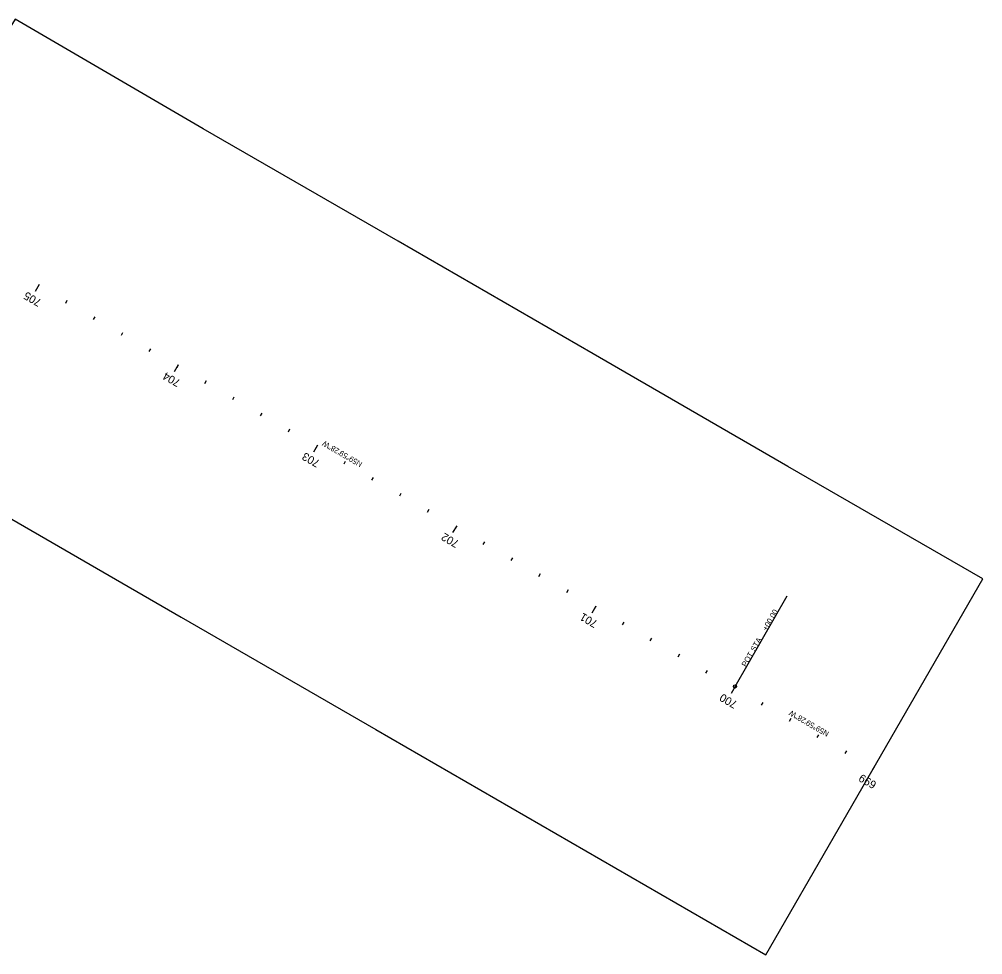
# Model space of a CAD drawing. Extents: x 2005522 to 2006988, y 402476 to 404900.
# Drawn here: x 2006388 to 2006988, y 402476 to 403058 of the extents above; entities that cross this region are included whole.
import ezdxf

# ---------------------------------------------------------------- set-up
doc = ezdxf.new("R2010")
doc.units = 0
for name, color, linetype in [('ClipDrawingBound_dp', 7, 'Continuous'), ('TextAlgnCardinalPnt', 7, 'Continuous'), ('TextAlgnStation100', 7, 'Continuous'), ('TextAlgnStation1000', 7, 'Continuous'), ('TextAlgnStation500', 7, 'Continuous'), ('TextAlgnStation5000', 7, 'Continuous'), ('TextAlgnTangent', 7, 'Continuous'), ('TextAlgnTicks100', 7, 'Continuous'), ('TextAlgnTicks1000', 7, 'Continuous'), ('TextAlgnTicks500', 7, 'Continuous'), ('TextAlgnTicks5000', 7, 'Continuous')]:
    doc.layers.add(name, color=color, linetype=linetype)

msp = doc.modelspace()

# ---------------------------------------------------------------- linework, layer by layer
at = {"layer": 'ClipDrawingBound_dp'}
msp.add_lwpolyline([(2006852.71, 402476.04), (2006987.75, 402709.84), (2006866.52, 402779.86), (2006745.28, 402849.88), (2006624.05, 402919.9), (2006502.82, 402989.92), (2006385.68, 403058.05), (2006242.95, 402828.86), (2006367.78, 402756.11), (2006489.01, 402686.09), (2006610.25, 402616.07), (2006731.48, 402546.06)], close=True, dxfattribs=at)
at = {"layer": 'TextAlgnCardinalPnt'}
msp.add_line((2006833.64, 402642.95), (2006866.14, 402699.24), dxfattribs=at)
msp.add_circle((2006833.64, 402642.95), 1, dxfattribs=at)
at = {"layer": 'TextAlgnTicks100'}
for p, q in [((2006400.66, 402893.02), (2006398.16, 402888.69)), ((2006417.98, 402883.02), (2006416.98, 402881.29)), ((2006435.3, 402873.01), (2006434.3, 402871.28)), ((2006452.62, 402863.01), (2006451.62, 402861.28)), ((2006469.94, 402853.01), (2006468.94, 402851.28)), ((2006487.26, 402843.01), (2006484.76, 402838.68)), ((2006504.58, 402833), (2006503.58, 402831.27)), ((2006521.89, 402823), (2006520.89, 402821.27)), ((2006539.21, 402813), (2006538.21, 402811.27)), ((2006556.53, 402803), (2006555.53, 402801.26)), ((2006573.85, 402792.99), (2006571.35, 402788.66)), ((2006591.17, 402782.99), (2006590.17, 402781.26)), ((2006608.49, 402772.99), (2006607.49, 402771.26)), ((2006625.81, 402762.99), (2006624.81, 402761.25)), ((2006643.13, 402752.98), (2006642.13, 402751.25)), ((2006660.45, 402742.98), (2006657.95, 402738.65)), ((2006677.76, 402732.98), (2006676.76, 402731.25)), ((2006695.08, 402722.97), (2006694.08, 402721.24)), ((2006712.4, 402712.97), (2006711.4, 402711.24)), ((2006729.72, 402702.97), (2006728.72, 402701.24)), ((2006747.04, 402692.97), (2006744.54, 402688.64)), ((2006764.36, 402682.96), (2006763.36, 402681.23)), ((2006781.68, 402672.96), (2006780.68, 402671.23)), ((2006799, 402662.96), (2006798, 402661.23)), ((2006816.32, 402652.96), (2006815.32, 402651.22)), ((2006833.64, 402642.95), (2006831.13, 402638.62)), ((2006850.95, 402632.95), (2006849.95, 402631.22)), ((2006868.27, 402622.95), (2006867.27, 402621.22)), ((2006885.59, 402612.95), (2006884.59, 402611.21)), ((2006902.91, 402602.94), (2006901.91, 402601.21)), ((2006920.23, 402592.94), (2006917.73, 402588.61))]:
    msp.add_line(p, q, dxfattribs=at)
at = {"layer": 'TextAlgnTicks1000'}
for p, q in [((2006487.26, 402843.01), (2006486.26, 402841.28)), ((2006660.45, 402742.98), (2006659.45, 402741.25)), ((2006833.64, 402642.95), (2006831.13, 402638.62))]:
    msp.add_line(p, q, dxfattribs=at)
at = {"layer": 'TextAlgnTicks500'}
for p, q in [((2006400.66, 402893.02), (2006398.16, 402888.69)), ((2006487.26, 402843.01), (2006486.26, 402841.28)), ((2006573.85, 402792.99), (2006572.85, 402791.26)), ((2006660.45, 402742.98), (2006659.45, 402741.25)), ((2006747.04, 402692.97), (2006746.04, 402691.23)), ((2006833.64, 402642.95), (2006831.13, 402638.62)), ((2006920.23, 402592.94), (2006919.23, 402591.21))]:
    msp.add_line(p, q, dxfattribs=at)
at = {"layer": 'TextAlgnTicks5000'}
msp.add_line((2006833.64, 402642.95), (2006831.13, 402638.62), dxfattribs=at)

# ---------------------------------------------------------------- texts
at = {"layer": 'TextAlgnCardinalPnt'}
for s, p in [('+00.00', (2006853.41, 402677.19)), (' STA. ', (2006845.34, 402663.23)), ('POT', (2006840.47, 402654.78))]:
    msp.add_text(s, height=3.48, rotation=59.99111, dxfattribs=at).set_placement(p)
at = {"layer": 'TextAlgnStation100'}
for s, p in [('705', (2006402.57, 402883.26)), ('704', (2006489.1, 402833.28)), ('703', (2006575.78, 402783.22)), ('702', (2006662.37, 402733.2)), ('701', (2006748.58, 402683.42)), ('700', (2006835.51, 402633.21)), ('699', (2006922.11, 402583.19))]:
    msp.add_text(s, height=4.98, rotation=149.99111, dxfattribs=at).set_placement(p)
at = {"layer": 'TextAlgnStation1000'}
msp.add_text('700', height=4.98, rotation=149.99111, dxfattribs=at).set_placement((2006835.51, 402633.21))
at = {"layer": 'TextAlgnStation500'}
for s, p in [('705', (2006402.57, 402883.26)), ('700', (2006835.51, 402633.21))]:
    msp.add_text(s, height=4.98, rotation=149.99111, dxfattribs=at).set_placement(p)
at = {"layer": 'TextAlgnStation5000'}
msp.add_text('700', height=4.98, rotation=149.99111, dxfattribs=at).set_placement((2006835.51, 402633.21))
at = {"layer": 'TextAlgnTangent'}
for p in [(2006602.09, 402782.22), (2006892.49, 402614.49)]:
    msp.add_text('N59°59\'28"W', height=3.48, rotation=149.99111, dxfattribs=at).set_placement(p)

doc.saveas('drawing.dxf')
